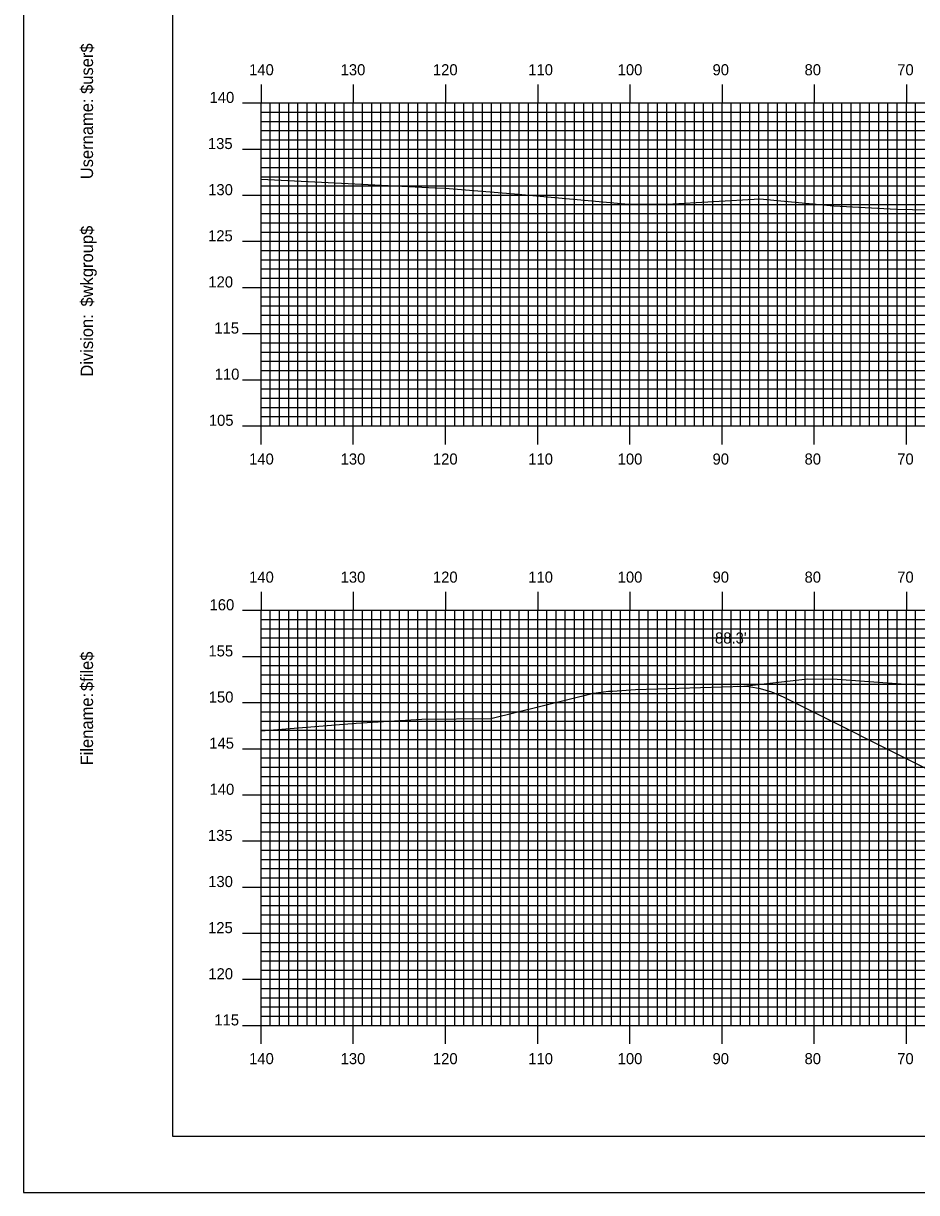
# Model space of a CAD drawing. Extents: x 1785402 to 1785745, y 442591 to 442811.
# Drawn here: x 1785401.8 to 1785498.6, y 442590.5 to 442717.3 of the extents above; entities that cross this region are included whole.
import ezdxf

# ---------------------------------------------------------------- set-up
doc = ezdxf.new("R2010")
doc.units = 0
for name, color, linetype in [('BORDER', 7, 'Continuous'), ('D_Roadway_SlopeLines', 7, 'Continuous'), ('D_Text_Standard', 7, 'Continuous'), ('H_V ANNOTATION', 7, 'Continuous'), ('MAJOR', 7, 'Continuous'), ('MINOR', 7, 'Continuous'), ('PLOT BOUNDARY', 7, 'Continuous'), ('S_Roadway_Centerline', 7, 'Continuous')]:
    doc.layers.add(name, color=color, linetype=linetype)

msp = doc.modelspace()

# ---------------------------------------------------------------- linework, layer by layer
at = {"layer": 'BORDER'}
msp.add_lwpolyline([(1785417.94, 442596.67), (1785737.94, 442596.67), (1785737.94, 442806.67), (1785417.94, 442806.67)], close=True, dxfattribs=at)
at = {"layer": 'D_Roadway_SlopeLines'}
msp.add_lwpolyline([(1785533.36, 442619.66), (1785484.2, 442644.25), (1785482.95, 442644.79), (1785481.7, 442645.17), (1785480.45, 442645.38), (1785479.2, 442645.42)], dxfattribs=at)
at = {"layer": 'MAJOR'}
for p, q in [((1785427.54, 442710.67), (1785427.54, 442708.67)), ((1785437.54, 442710.67), (1785437.54, 442708.67)), ((1785447.54, 442710.67), (1785447.54, 442708.67)), ((1785457.54, 442710.67), (1785457.54, 442708.67)), ((1785467.54, 442710.67), (1785467.54, 442708.67)), ((1785477.54, 442710.67), (1785477.54, 442708.67)), ((1785487.54, 442710.67), (1785487.54, 442708.67)), ((1785497.54, 442710.67), (1785497.54, 442708.67)), ((1785425.53, 442708.67), (1785427.54, 442708.67)), ((1785427.54, 442708.67), (1785707.54, 442708.67)), ((1785427.54, 442673.67), (1785427.54, 442708.67)), ((1785427.54, 442673.67), (1785427.54, 442708.67)), ((1785427.54, 442708.67), (1785707.54, 442708.67)), ((1785437.54, 442673.67), (1785437.54, 442708.67)), ((1785447.54, 442673.67), (1785447.54, 442708.67)), ((1785457.54, 442673.67), (1785457.54, 442708.67)), ((1785467.54, 442673.67), (1785467.54, 442708.67)), ((1785477.54, 442673.67), (1785477.54, 442708.67)), ((1785487.54, 442673.67), (1785487.54, 442708.67)), ((1785497.54, 442673.67), (1785497.54, 442708.67)), ((1785425.53, 442703.67), (1785427.54, 442703.67)), ((1785427.54, 442703.67), (1785707.54, 442703.67)), ((1785425.53, 442698.67), (1785427.54, 442698.67)), ((1785427.54, 442698.67), (1785707.54, 442698.67)), ((1785425.53, 442693.67), (1785427.54, 442693.67)), ((1785427.54, 442693.67), (1785707.54, 442693.67)), ((1785425.53, 442688.67), (1785427.54, 442688.67)), ((1785427.54, 442688.67), (1785707.54, 442688.67)), ((1785425.53, 442683.67), (1785427.54, 442683.67)), ((1785427.54, 442683.67), (1785707.54, 442683.67)), ((1785425.53, 442678.67), (1785427.54, 442678.67)), ((1785427.54, 442678.67), (1785707.54, 442678.67)), ((1785425.53, 442673.67), (1785427.54, 442673.67)), ((1785427.54, 442673.67), (1785707.54, 442673.67)), ((1785427.54, 442673.67), (1785707.54, 442673.67)), ((1785427.54, 442671.66), (1785427.54, 442673.67)), ((1785437.54, 442671.66), (1785437.54, 442673.67)), ((1785447.54, 442671.66), (1785447.54, 442673.67)), ((1785457.54, 442671.66), (1785457.54, 442673.67)), ((1785467.54, 442671.66), (1785467.54, 442673.67)), ((1785477.54, 442671.66), (1785477.54, 442673.67)), ((1785487.54, 442671.66), (1785487.54, 442673.67)), ((1785497.54, 442671.66), (1785497.54, 442673.67)), ((1785427.54, 442655.67), (1785427.54, 442653.67)), ((1785437.54, 442655.67), (1785437.54, 442653.67)), ((1785447.54, 442655.67), (1785447.54, 442653.67)), ((1785457.54, 442655.67), (1785457.54, 442653.67)), ((1785467.54, 442655.67), (1785467.54, 442653.67)), ((1785477.54, 442655.67), (1785477.54, 442653.67)), ((1785487.54, 442655.67), (1785487.54, 442653.67)), ((1785497.54, 442655.67), (1785497.54, 442653.67)), ((1785425.53, 442653.67), (1785427.54, 442653.67)), ((1785427.54, 442653.67), (1785707.54, 442653.67)), ((1785427.54, 442608.67), (1785427.54, 442653.67)), ((1785427.54, 442608.67), (1785427.54, 442653.67)), ((1785427.54, 442653.67), (1785707.54, 442653.67)), ((1785437.54, 442608.67), (1785437.54, 442653.67)), ((1785447.54, 442608.67), (1785447.54, 442653.67)), ((1785457.54, 442608.67), (1785457.54, 442653.67)), ((1785467.54, 442608.67), (1785467.54, 442653.67)), ((1785477.54, 442608.67), (1785477.54, 442653.67)), ((1785487.54, 442608.67), (1785487.54, 442653.67)), ((1785497.54, 442608.67), (1785497.54, 442653.67)), ((1785425.53, 442648.67), (1785427.54, 442648.67)), ((1785427.54, 442648.67), (1785707.54, 442648.67)), ((1785425.53, 442643.67), (1785427.54, 442643.67)), ((1785427.54, 442643.67), (1785707.54, 442643.67)), ((1785425.53, 442638.67), (1785427.54, 442638.67)), ((1785427.54, 442638.67), (1785707.54, 442638.67)), ((1785425.53, 442633.67), (1785427.54, 442633.67)), ((1785427.54, 442633.67), (1785707.54, 442633.67)), ((1785425.53, 442628.67), (1785427.54, 442628.67)), ((1785427.54, 442628.67), (1785707.54, 442628.67)), ((1785425.53, 442623.67), (1785427.54, 442623.67)), ((1785427.54, 442623.67), (1785707.54, 442623.67)), ((1785425.53, 442618.67), (1785427.54, 442618.67)), ((1785427.54, 442618.67), (1785707.54, 442618.67)), ((1785425.53, 442613.67), (1785427.54, 442613.67)), ((1785427.54, 442613.67), (1785707.54, 442613.67)), ((1785425.53, 442608.67), (1785427.54, 442608.67)), ((1785427.54, 442608.67), (1785707.54, 442608.67)), ((1785427.54, 442608.67), (1785707.54, 442608.67)), ((1785427.54, 442606.66), (1785427.54, 442608.67)), ((1785437.54, 442606.66), (1785437.54, 442608.67)), ((1785447.54, 442606.66), (1785447.54, 442608.67)), ((1785457.54, 442606.66), (1785457.54, 442608.67)), ((1785467.54, 442606.66), (1785467.54, 442608.67)), ((1785477.54, 442606.66), (1785477.54, 442608.67)), ((1785487.54, 442606.66), (1785487.54, 442608.67)), ((1785497.54, 442606.66), (1785497.54, 442608.67))]:
    msp.add_line(p, q, dxfattribs=at)
at = {"layer": 'MINOR'}
for p, q in [((1785428.54, 442673.67), (1785428.54, 442708.67)), ((1785429.54, 442673.67), (1785429.54, 442708.67)), ((1785430.54, 442673.67), (1785430.54, 442708.67)), ((1785431.54, 442673.67), (1785431.54, 442708.67)), ((1785432.54, 442673.67), (1785432.54, 442708.67)), ((1785433.54, 442673.67), (1785433.54, 442708.67)), ((1785434.54, 442673.67), (1785434.54, 442708.67)), ((1785435.54, 442673.67), (1785435.54, 442708.67)), ((1785436.54, 442673.67), (1785436.54, 442708.67)), ((1785438.54, 442673.67), (1785438.54, 442708.67)), ((1785439.54, 442673.67), (1785439.54, 442708.67)), ((1785440.54, 442673.67), (1785440.54, 442708.67)), ((1785441.54, 442673.67), (1785441.54, 442708.67)), ((1785442.54, 442673.67), (1785442.54, 442708.67)), ((1785443.54, 442673.67), (1785443.54, 442708.67)), ((1785444.54, 442673.67), (1785444.54, 442708.67)), ((1785445.54, 442673.67), (1785445.54, 442708.67)), ((1785446.54, 442673.67), (1785446.54, 442708.67)), ((1785448.54, 442673.67), (1785448.54, 442708.67)), ((1785449.54, 442673.67), (1785449.54, 442708.67)), ((1785450.54, 442673.67), (1785450.54, 442708.67)), ((1785451.54, 442673.67), (1785451.54, 442708.67)), ((1785452.54, 442673.67), (1785452.54, 442708.67)), ((1785453.54, 442673.67), (1785453.54, 442708.67)), ((1785454.54, 442673.67), (1785454.54, 442708.67)), ((1785455.54, 442673.67), (1785455.54, 442708.67)), ((1785456.54, 442673.67), (1785456.54, 442708.67)), ((1785458.54, 442673.67), (1785458.54, 442708.67)), ((1785459.54, 442673.67), (1785459.54, 442708.67)), ((1785460.54, 442673.67), (1785460.54, 442708.67)), ((1785461.54, 442673.67), (1785461.54, 442708.67)), ((1785462.54, 442673.67), (1785462.54, 442708.67)), ((1785463.54, 442673.67), (1785463.54, 442708.67)), ((1785464.54, 442673.67), (1785464.54, 442708.67)), ((1785465.54, 442673.67), (1785465.54, 442708.67)), ((1785466.54, 442673.67), (1785466.54, 442708.67)), ((1785468.54, 442673.67), (1785468.54, 442708.67)), ((1785469.54, 442673.67), (1785469.54, 442708.67)), ((1785470.54, 442673.67), (1785470.54, 442708.67)), ((1785471.54, 442673.67), (1785471.54, 442708.67)), ((1785472.54, 442673.67), (1785472.54, 442708.67)), ((1785473.54, 442673.67), (1785473.54, 442708.67)), ((1785474.54, 442673.67), (1785474.54, 442708.67)), ((1785475.54, 442673.67), (1785475.54, 442708.67)), ((1785476.54, 442673.67), (1785476.54, 442708.67)), ((1785478.54, 442673.67), (1785478.54, 442708.67)), ((1785479.54, 442673.67), (1785479.54, 442708.67)), ((1785480.54, 442673.67), (1785480.54, 442708.67)), ((1785481.54, 442673.67), (1785481.54, 442708.67)), ((1785482.54, 442673.67), (1785482.54, 442708.67)), ((1785483.54, 442673.67), (1785483.54, 442708.67)), ((1785484.54, 442673.67), (1785484.54, 442708.67)), ((1785485.54, 442673.67), (1785485.54, 442708.67)), ((1785486.54, 442673.67), (1785486.54, 442708.67)), ((1785488.54, 442673.67), (1785488.54, 442708.67)), ((1785489.54, 442673.67), (1785489.54, 442708.67)), ((1785490.54, 442673.67), (1785490.54, 442708.67)), ((1785491.54, 442673.67), (1785491.54, 442708.67)), ((1785492.54, 442673.67), (1785492.54, 442708.67)), ((1785493.54, 442673.67), (1785493.54, 442708.67)), ((1785494.54, 442673.67), (1785494.54, 442708.67)), ((1785495.54, 442673.67), (1785495.54, 442708.67)), ((1785496.54, 442673.67), (1785496.54, 442708.67)), ((1785498.54, 442673.67), (1785498.54, 442708.67)), ((1785427.54, 442707.67), (1785707.54, 442707.67)), ((1785427.54, 442707.67), (1785429.54, 442707.67)), ((1785427.54, 442706.67), (1785707.54, 442706.67)), ((1785427.54, 442706.67), (1785429.54, 442706.67)), ((1785427.54, 442705.67), (1785707.54, 442705.67)), ((1785427.54, 442705.67), (1785429.54, 442705.67)), ((1785427.54, 442704.67), (1785707.54, 442704.67)), ((1785427.54, 442704.67), (1785429.54, 442704.67)), ((1785427.54, 442702.67), (1785707.54, 442702.67)), ((1785427.54, 442702.67), (1785429.54, 442702.67)), ((1785427.54, 442701.67), (1785707.54, 442701.67)), ((1785427.54, 442701.67), (1785429.54, 442701.67)), ((1785427.54, 442700.67), (1785707.54, 442700.67)), ((1785427.54, 442700.67), (1785429.54, 442700.67)), ((1785427.54, 442699.67), (1785707.54, 442699.67)), ((1785427.54, 442699.67), (1785429.54, 442699.67)), ((1785427.54, 442697.67), (1785707.54, 442697.67)), ((1785427.54, 442697.67), (1785429.54, 442697.67)), ((1785427.54, 442696.67), (1785707.54, 442696.67)), ((1785427.54, 442696.67), (1785429.54, 442696.67)), ((1785427.54, 442695.67), (1785707.54, 442695.67)), ((1785427.54, 442695.67), (1785429.54, 442695.67)), ((1785427.54, 442694.67), (1785707.54, 442694.67)), ((1785427.54, 442694.67), (1785429.54, 442694.67)), ((1785427.54, 442692.67), (1785707.54, 442692.67)), ((1785427.54, 442692.67), (1785429.54, 442692.67)), ((1785427.54, 442691.67), (1785707.54, 442691.67)), ((1785427.54, 442691.67), (1785429.54, 442691.67)), ((1785427.54, 442690.67), (1785707.54, 442690.67)), ((1785427.54, 442690.67), (1785429.54, 442690.67)), ((1785427.54, 442689.67), (1785707.54, 442689.67)), ((1785427.54, 442689.67), (1785429.54, 442689.67)), ((1785427.54, 442687.67), (1785707.54, 442687.67)), ((1785427.54, 442687.67), (1785429.54, 442687.67)), ((1785427.54, 442686.67), (1785707.54, 442686.67)), ((1785427.54, 442686.67), (1785429.54, 442686.67)), ((1785427.54, 442685.67), (1785707.54, 442685.67)), ((1785427.54, 442685.67), (1785429.54, 442685.67)), ((1785427.54, 442684.67), (1785707.54, 442684.67)), ((1785427.54, 442684.67), (1785429.54, 442684.67)), ((1785427.54, 442682.67), (1785707.54, 442682.67)), ((1785427.54, 442682.67), (1785429.54, 442682.67)), ((1785427.54, 442681.67), (1785707.54, 442681.67)), ((1785427.54, 442681.67), (1785429.54, 442681.67)), ((1785427.54, 442680.67), (1785707.54, 442680.67)), ((1785427.54, 442680.67), (1785429.54, 442680.67)), ((1785427.54, 442679.67), (1785707.54, 442679.67)), ((1785427.54, 442679.67), (1785429.54, 442679.67)), ((1785427.54, 442677.67), (1785707.54, 442677.67)), ((1785427.54, 442677.67), (1785429.54, 442677.67)), ((1785427.54, 442676.67), (1785707.54, 442676.67)), ((1785427.54, 442676.67), (1785429.54, 442676.67)), ((1785427.54, 442675.67), (1785707.54, 442675.67)), ((1785427.54, 442675.67), (1785429.54, 442675.67)), ((1785427.54, 442674.67), (1785707.54, 442674.67)), ((1785427.54, 442674.67), (1785429.54, 442674.67)), ((1785428.54, 442608.67), (1785428.54, 442653.67)), ((1785429.54, 442608.67), (1785429.54, 442653.67)), ((1785430.54, 442608.67), (1785430.54, 442653.67)), ((1785431.54, 442608.67), (1785431.54, 442653.67)), ((1785432.54, 442608.67), (1785432.54, 442653.67)), ((1785433.54, 442608.67), (1785433.54, 442653.67)), ((1785434.54, 442608.67), (1785434.54, 442653.67)), ((1785435.54, 442608.67), (1785435.54, 442653.67)), ((1785436.54, 442608.67), (1785436.54, 442653.67)), ((1785438.54, 442608.67), (1785438.54, 442653.67)), ((1785439.54, 442608.67), (1785439.54, 442653.67)), ((1785440.54, 442608.67), (1785440.54, 442653.67)), ((1785441.54, 442608.67), (1785441.54, 442653.67)), ((1785442.54, 442608.67), (1785442.54, 442653.67)), ((1785443.54, 442608.67), (1785443.54, 442653.67)), ((1785444.54, 442608.67), (1785444.54, 442653.67)), ((1785445.54, 442608.67), (1785445.54, 442653.67)), ((1785446.54, 442608.67), (1785446.54, 442653.67)), ((1785448.54, 442608.67), (1785448.54, 442653.67)), ((1785449.54, 442608.67), (1785449.54, 442653.67)), ((1785450.54, 442608.67), (1785450.54, 442653.67)), ((1785451.54, 442608.67), (1785451.54, 442653.67)), ((1785452.54, 442608.67), (1785452.54, 442653.67)), ((1785453.54, 442608.67), (1785453.54, 442653.67)), ((1785454.54, 442608.67), (1785454.54, 442653.67)), ((1785455.54, 442608.67), (1785455.54, 442653.67)), ((1785456.54, 442608.67), (1785456.54, 442653.67)), ((1785458.54, 442608.67), (1785458.54, 442653.67)), ((1785459.54, 442608.67), (1785459.54, 442653.67)), ((1785460.54, 442608.67), (1785460.54, 442653.67)), ((1785461.54, 442608.67), (1785461.54, 442653.67)), ((1785462.54, 442608.67), (1785462.54, 442653.67)), ((1785463.54, 442608.67), (1785463.54, 442653.67)), ((1785464.54, 442608.67), (1785464.54, 442653.67)), ((1785465.54, 442608.67), (1785465.54, 442653.67)), ((1785466.54, 442608.67), (1785466.54, 442653.67)), ((1785468.54, 442608.67), (1785468.54, 442653.67)), ((1785469.54, 442608.67), (1785469.54, 442653.67)), ((1785470.54, 442608.67), (1785470.54, 442653.67)), ((1785471.54, 442608.67), (1785471.54, 442653.67)), ((1785472.54, 442608.67), (1785472.54, 442653.67)), ((1785473.54, 442608.67), (1785473.54, 442653.67)), ((1785474.54, 442608.67), (1785474.54, 442653.67)), ((1785475.54, 442608.67), (1785475.54, 442653.67)), ((1785476.54, 442608.67), (1785476.54, 442653.67)), ((1785478.54, 442608.67), (1785478.54, 442653.67)), ((1785479.54, 442608.67), (1785479.54, 442653.67)), ((1785480.54, 442608.67), (1785480.54, 442653.67)), ((1785481.54, 442608.67), (1785481.54, 442653.67)), ((1785482.54, 442608.67), (1785482.54, 442653.67)), ((1785483.54, 442608.67), (1785483.54, 442653.67)), ((1785484.54, 442608.67), (1785484.54, 442653.67)), ((1785485.54, 442608.67), (1785485.54, 442653.67)), ((1785486.54, 442608.67), (1785486.54, 442653.67)), ((1785488.54, 442608.67), (1785488.54, 442653.67)), ((1785489.54, 442608.67), (1785489.54, 442653.67)), ((1785490.54, 442608.67), (1785490.54, 442653.67)), ((1785491.54, 442608.67), (1785491.54, 442653.67)), ((1785492.54, 442608.67), (1785492.54, 442653.67)), ((1785493.54, 442608.67), (1785493.54, 442653.67)), ((1785494.54, 442608.67), (1785494.54, 442653.67)), ((1785495.54, 442608.67), (1785495.54, 442653.67)), ((1785496.54, 442608.67), (1785496.54, 442653.67)), ((1785498.54, 442608.67), (1785498.54, 442653.67)), ((1785427.54, 442652.67), (1785707.54, 442652.67)), ((1785427.54, 442652.67), (1785429.54, 442652.67)), ((1785427.54, 442651.67), (1785707.54, 442651.67)), ((1785427.54, 442651.67), (1785429.54, 442651.67)), ((1785427.54, 442650.67), (1785707.54, 442650.67)), ((1785427.54, 442650.67), (1785429.54, 442650.67)), ((1785427.54, 442649.67), (1785707.54, 442649.67)), ((1785427.54, 442649.67), (1785429.54, 442649.67)), ((1785427.54, 442647.67), (1785707.54, 442647.67)), ((1785427.54, 442647.67), (1785429.54, 442647.67)), ((1785427.54, 442646.67), (1785707.54, 442646.67)), ((1785427.54, 442646.67), (1785429.54, 442646.67)), ((1785427.54, 442645.67), (1785707.54, 442645.67)), ((1785427.54, 442645.67), (1785429.54, 442645.67)), ((1785427.54, 442644.67), (1785707.54, 442644.67)), ((1785427.54, 442644.67), (1785429.54, 442644.67)), ((1785427.54, 442642.67), (1785707.54, 442642.67)), ((1785427.54, 442642.67), (1785429.54, 442642.67)), ((1785427.54, 442641.67), (1785707.54, 442641.67)), ((1785427.54, 442641.67), (1785429.54, 442641.67)), ((1785427.54, 442640.67), (1785707.54, 442640.67)), ((1785427.54, 442640.67), (1785429.54, 442640.67)), ((1785427.54, 442639.67), (1785707.54, 442639.67)), ((1785427.54, 442639.67), (1785429.54, 442639.67)), ((1785427.54, 442637.67), (1785707.54, 442637.67)), ((1785427.54, 442637.67), (1785429.54, 442637.67)), ((1785427.54, 442636.67), (1785707.54, 442636.67)), ((1785427.54, 442636.67), (1785429.54, 442636.67)), ((1785427.54, 442635.67), (1785707.54, 442635.67)), ((1785427.54, 442635.67), (1785429.54, 442635.67)), ((1785427.54, 442634.67), (1785707.54, 442634.67)), ((1785427.54, 442634.67), (1785429.54, 442634.67)), ((1785427.54, 442632.67), (1785707.54, 442632.67)), ((1785427.54, 442632.67), (1785429.54, 442632.67)), ((1785427.54, 442631.67), (1785707.54, 442631.67)), ((1785427.54, 442631.67), (1785429.54, 442631.67)), ((1785427.54, 442630.67), (1785707.54, 442630.67)), ((1785427.54, 442630.67), (1785429.54, 442630.67)), ((1785427.54, 442629.67), (1785707.54, 442629.67)), ((1785427.54, 442629.67), (1785429.54, 442629.67)), ((1785427.54, 442627.67), (1785707.54, 442627.67)), ((1785427.54, 442627.67), (1785429.54, 442627.67)), ((1785427.54, 442626.67), (1785707.54, 442626.67)), ((1785427.54, 442626.67), (1785429.54, 442626.67)), ((1785427.54, 442625.67), (1785707.54, 442625.67)), ((1785427.54, 442625.67), (1785429.54, 442625.67)), ((1785427.54, 442624.67), (1785707.54, 442624.67)), ((1785427.54, 442624.67), (1785429.54, 442624.67)), ((1785427.54, 442622.67), (1785707.54, 442622.67)), ((1785427.54, 442622.67), (1785429.54, 442622.67)), ((1785427.54, 442621.67), (1785707.54, 442621.67)), ((1785427.54, 442621.67), (1785429.54, 442621.67)), ((1785427.54, 442620.67), (1785707.54, 442620.67)), ((1785427.54, 442620.67), (1785429.54, 442620.67)), ((1785427.54, 442619.67), (1785707.54, 442619.67)), ((1785427.54, 442619.67), (1785429.54, 442619.67)), ((1785427.54, 442617.67), (1785707.54, 442617.67)), ((1785427.54, 442617.67), (1785429.54, 442617.67)), ((1785427.54, 442616.67), (1785707.54, 442616.67)), ((1785427.54, 442616.67), (1785429.54, 442616.67)), ((1785427.54, 442615.67), (1785707.54, 442615.67)), ((1785427.54, 442615.67), (1785429.54, 442615.67)), ((1785427.54, 442614.67), (1785707.54, 442614.67)), ((1785427.54, 442614.67), (1785429.54, 442614.67)), ((1785427.54, 442612.67), (1785707.54, 442612.67)), ((1785427.54, 442612.67), (1785429.54, 442612.67)), ((1785427.54, 442611.67), (1785707.54, 442611.67)), ((1785427.54, 442611.67), (1785429.54, 442611.67)), ((1785427.54, 442610.67), (1785707.54, 442610.67)), ((1785427.54, 442610.67), (1785429.54, 442610.67)), ((1785427.54, 442609.67), (1785707.54, 442609.67)), ((1785427.54, 442609.67), (1785429.54, 442609.67))]:
    msp.add_line(p, q, dxfattribs=at)
at = {"layer": 'PLOT BOUNDARY'}
msp.add_lwpolyline([(1785401.75, 442590.55), (1785741.75, 442590.55), (1785741.75, 442810.55), (1785401.75, 442810.55)], close=True, dxfattribs=at)
at = {"layer": 'S_Roadway_Centerline'}
for points in [[(1785427.54, 442700.39), (1785446.41, 442699.48), (1785447.49, 442699.44), (1785455.03, 442698.81), (1785467.38, 442697.7), (1785469.16, 442697.68), (1785471.57, 442697.7), (1785481.63, 442698.29), (1785489.68, 442697.53), (1785496.45, 442697.16), (1785510.26, 442696.88), (1785519.01, 442697.09), (1785536.92, 442694.88), (1785548.31, 442694.01), (1785553.52, 442693.96), (1785563.17, 442693.89), (1785574.43, 442693.48), (1785576.28, 442693.43), (1785594.5, 442691.22), (1785603.28, 442690.91), (1785609.96, 442691.19), (1785616.82, 442690.7), (1785633.18, 442689.06)], [(1785427.54, 442640.61), (1785437.84, 442641.43), (1785444.97, 442641.86), (1785452.46, 442641.95), (1785463.61, 442644.69), (1785465.23, 442644.89), (1785465.64, 442644.92), (1785468.14, 442645.09), (1785479.91, 442645.44), (1785486.82, 442646.25), (1785490.01, 442646.21), (1785497.48, 442645.68), (1785499.86, 442645.6)]]:
    msp.add_lwpolyline(points, dxfattribs=at)

# ---------------------------------------------------------------- texts
at = {"layer": 'BORDER'}
for s, p in [('$user$', (1785409.31, 442709.65)), ('$user$', (1785409.31, 442709.65)), ('Username:', (1785409.31, 442700.4)), ('Username:', (1785409.31, 442700.4)), ('$wkgroup$', (1785409.31, 442686.6)), ('$wkgroup$', (1785409.31, 442686.6)), ('Division:', (1785409.31, 442679)), ('Division:', (1785409.31, 442679)), ('$file$', (1785409.31, 442644.92)), ('$file$', (1785409.31, 442644.92)), ('Filename:', (1785409.31, 442636.86)), ('Filename:', (1785409.31, 442636.86))]:
    msp.add_text(s, height=1.339, rotation=90, dxfattribs=at).set_placement(p)
at = {"layer": 'D_Text_Standard'}
msp.add_text("88.3'", height=1.2, dxfattribs=at).set_placement((1785476.78, 442650.07))
at = {"layer": 'H_V ANNOTATION'}
for s, p in [('140', (1785426.24, 442711.67)), ('130', (1785436.17, 442711.67)), ('120', (1785446.18, 442711.67)), ('110', (1785456.52, 442711.67)), ('100', (1785466.22, 442711.67)), ('90', (1785476.51, 442711.67)), ('80', (1785486.49, 442711.67)), ('70', (1785496.54, 442711.67)), ('140', (1785421.95, 442708.67)), ('135', (1785421.77, 442703.67)), ('130', (1785421.8, 442698.67)), ('125', (1785421.79, 442693.67)), ('120', (1785421.82, 442688.67)), ('115', (1785422.47, 442683.67)), ('110', (1785422.51, 442678.67)), ('105', (1785421.87, 442673.67)), ('140', (1785426.24, 442669.47)), ('130', (1785436.17, 442669.47)), ('120', (1785446.18, 442669.47)), ('110', (1785456.52, 442669.47)), ('100', (1785466.22, 442669.47)), ('90', (1785476.51, 442669.47)), ('80', (1785486.49, 442669.47)), ('70', (1785496.54, 442669.47)), ('140', (1785426.24, 442656.67)), ('130', (1785436.17, 442656.67)), ('120', (1785446.18, 442656.67)), ('110', (1785456.52, 442656.67)), ('100', (1785466.22, 442656.67)), ('90', (1785476.51, 442656.67)), ('80', (1785486.49, 442656.67)), ('70', (1785496.54, 442656.67)), ('160', (1785421.95, 442653.67)), ('155', (1785421.83, 442648.67)), ('150', (1785421.86, 442643.67)), ('145', (1785421.92, 442638.67)), ('140', (1785421.95, 442633.67)), ('135', (1785421.77, 442628.67)), ('130', (1785421.8, 442623.67)), ('125', (1785421.79, 442618.67)), ('120', (1785421.82, 442613.67)), ('115', (1785422.47, 442608.67)), ('140', (1785426.24, 442604.47)), ('130', (1785436.17, 442604.47)), ('120', (1785446.18, 442604.47)), ('110', (1785456.52, 442604.47)), ('100', (1785466.22, 442604.47)), ('90', (1785476.51, 442604.47)), ('80', (1785486.49, 442604.47)), ('70', (1785496.54, 442604.47))]:
    msp.add_text(s, height=1.2, dxfattribs=at).set_placement(p)
at = {"layer": 'MAJOR'}
for p in [(1785427.53, 442673.67), (1785427.53, 442608.67)]:
    msp.add_text('-', height=0.012, dxfattribs=at).set_placement(p)

doc.saveas('drawing.dxf')
